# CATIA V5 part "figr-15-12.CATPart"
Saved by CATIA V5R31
Part number: Part1
Bounding box of the stored display mesh (mm): x -50 to 50, y -32.5 to 33.5, z -52 to 1
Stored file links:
  D:\PROJECTS\Project 2021\US EDITION\CATIA V5 6R 2021\Resources\Part Files\c15_catia_v5_6r2021_prt\figr-15-12.CATPart
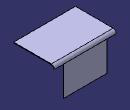
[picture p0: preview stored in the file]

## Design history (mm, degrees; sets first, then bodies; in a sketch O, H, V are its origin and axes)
SheetMetalParameters1: Thickness 1, BendRadius 4, KFactor 0.475772 {= log(min(100,max(20*SheetMetalParameters1.BendRadius,SheetMetalParameters1.Thickness)/SheetMetalParameters1.Thickness))/log(100)/2}, ReliefRadialLength 4, ReliefAxialLength 4, MinimumBendRadius 0
Body1 (main body)
  Sketch1 on xy-plane, origin (0, 0, 0), H (1, 0, 0), V (0, 1, 0)
    line L1 (-50, 32.5) -> (50, 32.5)
    line L2 (50, 32.5) -> (50, -32.5)
    line L3 (50, -32.5) -> (-50, -32.5)
    line L4 (-50, -32.5) -> (-50, 32.5)
    length L1 = 100
    length L2 = 65
    horizontal: L1 H, L3 H
    vertical: L2 V, L4 V
    symmetry: L4 L2 V, L1 L3 H
  Wall1: Thickness 1, Profile Sketch1
  d_NewWallOnEdge1: NewWallOnEdge_Edge edge [face of Wall1 | face of Wall1], NewWallOnEdge_Length 53, NewWallOnEdge_HeightLimitOffset 0, NewWallOnEdge_WidthOffset1 -15, NewWallOnEdge_WidthOffset2 -15, NewWallOnEdge_Angle 90, NewWallOnEdge_BendRadiusValue 4 {= SheetMetalParameters1.BendRadius}, NewWallOnEdge_BendTable SheetMetalParameters1, KFacteur 0.475772 {= log(min(100,max(20*d_NewWallOnEdge1.Radius,SheetMetalParameters1.Thickness)/SheetMetalParameters1.Thickness))/log(100)/2}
